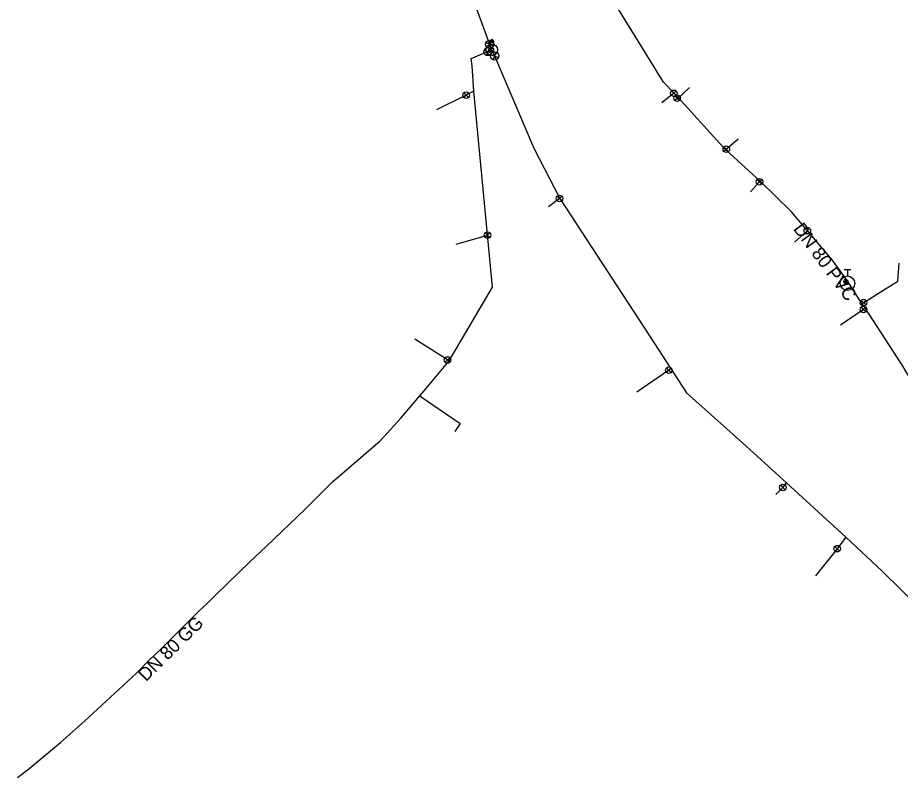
# Model space of a CAD drawing. Extents: x -484784 to -484458, y -1128042 to -1127614.
# Drawn here: x -484753.5 to -484646.3, y -1127810.6 to -1127718.4 of the extents above; entities that cross this region are included whole.
import ezdxf

# ---------------------------------------------------------------- set-up
doc = ezdxf.new("R2010")
doc.units = 0
for name, color, linetype in [('_hydrantova_odbocka_', 7, 'Continuous'), ('_pripojka_prevzato_z_dokumentace_', 7, 'Continuous'), ('_pripojka_priblizne_', 7, 'Continuous'), ('_voda_smvak_prevzato_z_dokumentace_', 7, 'Continuous'), ('Default', 7, 'Continuous'), ('MoLevel 27', 7, 'Continuous'), ('MoLevel 28', 7, 'Continuous'), ('MoLevel 30', 7, 'Continuous'), ('MoLevel 42', 7, 'Continuous'), ('MoLevel 46', 7, 'Continuous'), ('MoLevel 53', 7, 'Continuous')]:
    doc.layers.add(name, color=color, linetype=linetype)

# ---------------------------------------------------------------- blocks, each defined once
blk = doc.blocks.new('_uzaver_')
at = {"layer": 'Default'}
for p, q in [((-0.000035, -0.000035), (0.000035, 0.000035)), ((0.000035, -0.000035), (-0.000035, 0.000035))]:
    blk.add_line(p, q, dxfattribs=at)
for radius in [0.00005, 0.0000025]:
    blk.add_circle((0, 0), radius, dxfattribs=at)
blk = doc.blocks.new('_uzaver_pripojka_')
at = {"layer": 'Default'}
for p, q in [((-0.000035, -0.000035), (0.000035, 0.000035)), ((0.000035, -0.000035), (-0.000035, 0.000035))]:
    blk.add_line(p, q, dxfattribs=at)
for radius in [0.00005, 0.0000025]:
    blk.add_circle((0, 0), radius, dxfattribs=at)
blk = doc.blocks.new('_hydrant_voda_')
at = {"layer": 'Default'}
for p, q in [((-0.0000225, 0.000095), (0.0000225, 0.000095)), ((0, 0.000095), (0, 0.00005))]:
    blk.add_line(p, q, dxfattribs=at)
blk.add_circle((0, 0), 0.00005, dxfattribs=at)
blk = doc.blocks.new('_sachta_voda_')
at = {"layer": 'Default'}
blk.add_line((-0.00001, 0.000045), (0.00001, 0.000045), dxfattribs=at)
blk.add_lwpolyline([(-0.00001, 0.000035), (-0.00001, 0.00005), (0, 0.000065), (0.00001, 0.00005), (0.00001, 0.000035)], dxfattribs=at)
blk.add_circle((0, 0), 0.000035, dxfattribs=at)
blk = doc.blocks.new('_poklop_voda_')
at = {"layer": 'Default'}
blk.add_lwpolyline([(-0.00002, 0.00002), (0.00002, 0.00002), (0.00002, -0.00002), (-0.00002, -0.00002), (-0.00002, 0.00002)], dxfattribs=at)

msp = doc.modelspace()

# ---------------------------------------------------------------- linework, layer by layer
at = {"layer": '_hydrantova_odbocka_'}
msp.add_lwpolyline([(-484652.74, -1127750.29), (-484652.91, -1127750.43), (-484652.7, -1127750.64)], dxfattribs=at)
at = {"layer": '_pripojka_prevzato_z_dokumentace_'}
msp.add_line((-484659.14, -1127745.67), (-484657.58, -1127744.26), dxfattribs=at)
for points in [[(-484673.29, -1127728.06), (-484673.4, -1127728.16), (-484673.47, -1127728.22), (-484673.38, -1127728.31), (-484671.88, -1127726.88)], [(-484698.08, -1127727.31), (-484699.02, -1127727.8), (-484702.63, -1127729.59)], [(-484673.76, -1127727.55), (-484673.8, -1127727.58), (-484675.26, -1127728.75)], [(-484667.45, -1127734.47), (-484667.42, -1127734.36), (-484665.99, -1127733.1)], [(-484663.3, -1127738.25), (-484663.4, -1127738.32), (-484664.48, -1127739.54)], [(-484687.62, -1127740.36), (-484687.68, -1127740.36), (-484689, -1127741.37)], [(-484649.04, -1127751.92), (-484646.57, -1127750.38), (-484646.44, -1127748.22)], [(-484650.95, -1127753.11), (-484650.76, -1127753), (-484649.04, -1127751.92)], [(-484650.61, -1127753.6), (-484650.75, -1127753.82), (-484653.53, -1127755.74)], [(-484674.21, -1127760.95), (-484674.41, -1127761.21), (-484678.28, -1127763.87)], [(-484661.39, -1127776.29), (-484660.56, -1127775.44), (-484660.1, -1127774.89)], [(-484652.89, -1127781.48), (-484653.94, -1127782.87), (-484656.59, -1127786.17)]]:
    msp.add_lwpolyline(points, dxfattribs=at)
at = {"layer": '_pripojka_priblizne_'}
msp.add_line((-484700.25, -1127745.89), (-484696.41, -1127744.81), dxfattribs=at)
for points in [[(-484701.07, -1127760.05), (-484701.29, -1127759.96), (-484705.25, -1127757.44)], [(-484704.64, -1127764.33), (-484704.47, -1127764.42), (-484699.74, -1127767.67), (-484700.4, -1127768.63)]]:
    msp.add_lwpolyline(points, dxfattribs=at)
at = {"layer": '_voda_smvak_prevzato_z_dokumentace_'}
for p, q in [((-484695.9, -1127722.31), (-484696.15, -1127721.64)), ((-484696.38, -1127722.52), (-484695.9, -1127722.31)), ((-484695.9, -1127722.31), (-484695.56, -1127723.04))]:
    msp.add_line(p, q, dxfattribs=at)
for points in [[(-484696.15, -1127721.64), (-484696.87, -1127719.68), (-484701.22, -1127707.9), (-484706.63, -1127694.26), (-484709.08, -1127689.93), (-484711.43, -1127684.86), (-484712.44, -1127683.11)], [(-484643.08, -1127765.34), (-484645.56, -1127761.38), (-484646.12, -1127760.52), (-484650.61, -1127753.6), (-484650.95, -1127753.11), (-484652.74, -1127750.29), (-484654.58, -1127747.8), (-484659.5, -1127741.98), (-484663.3, -1127738.25), (-484667.45, -1127734.47), (-484668.22, -1127733.67), (-484673.26, -1127728.1), (-484673.76, -1127727.55), (-484675.04, -1127726.21), (-484681.24, -1127716.17), (-484682.76, -1127712.65), (-484683.58, -1127711.28), (-484684.33, -1127709.73), (-484687.86, -1127701.92), (-484687.92, -1127701.76), (-484691.71, -1127695.75), (-484698.39, -1127690.88), (-484712.1, -1127682.86)], [(-484753.49, -1127810.63), (-484753.17, -1127810.41), (-484752.12, -1127809.61), (-484748.28, -1127806.41), (-484745.39, -1127803.79), (-484739.05, -1127797.97), (-484737.46, -1127796.37), (-484736.15, -1127795.09), (-484731.43, -1127790.43), (-484730.44, -1127789.47), (-484729.4, -1127788.46), (-484725.31, -1127784.47), (-484723.32, -1127782.6), (-484718.57, -1127778.07), (-484715.25, -1127774.76), (-484709.45, -1127769.78), (-484706.97, -1127767.02), (-484704.64, -1127764.33), (-484704.1, -1127763.7), (-484701.07, -1127760.05), (-484695.81, -1127751.1), (-484698.08, -1127727.31), (-484698.29, -1127724.26), (-484698.39, -1127723.37), (-484696.38, -1127722.52)], [(-484695.56, -1127723.04), (-484690.81, -1127734.23), (-484687.62, -1127740.36), (-484676.16, -1127757.95), (-484674.21, -1127760.95), (-484672.26, -1127763.95), (-484665.44, -1127770.01), (-484660.1, -1127774.89), (-484652.89, -1127781.48), (-484648.49, -1127785.58), (-484632.11, -1127801.7)]]:
    msp.add_lwpolyline(points, dxfattribs=at)

# ---------------------------------------------------------------- block references
at = {"layer": 'MoLevel 27'}
for p, xscale, yscale, rotation in [((-484696.38, -1127722.52), 9999.999999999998, 9999.999999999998, -156.97097945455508), ((-484696.15, -1127721.64), 10000, 10000, 110.303081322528), ((-484695.56, -1127723.04), 10000.000000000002, 9999.999999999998, -67.18593646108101), ((-484652.91, -1127750.43), 5000, 5000, -45.00000001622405)]:
    msp.add_blockref('_uzaver_', p, dxfattribs=dict(at, xscale=xscale, yscale=yscale, rotation=rotation))
at = {"layer": 'MoLevel 28', "xscale": 17636.68430335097, "yscale": 17636.68430335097}
msp.add_blockref('_hydrant_voda_', (-484652.7, -1127750.64), dxfattribs=at)
at = {"layer": 'MoLevel 30', "xscale": 20000, "yscale": 20000}
msp.add_blockref('_sachta_voda_', (-484695.9, -1127722.31), dxfattribs=at)
at = {"layer": 'MoLevel 42', "xscale": 10000, "yscale": 10000}
msp.add_blockref('_poklop_voda_', (-484695.9, -1127722.31), dxfattribs=at)
at = {"layer": 'MoLevel 53', "xscale": 7999.999999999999, "yscale": 7999.999999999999}
for p in [(-484673.8, -1127727.58), (-484699.02, -1127727.8), (-484673.4, -1127728.16), (-484667.42, -1127734.36), (-484663.4, -1127738.32), (-484687.68, -1127740.36), (-484696.41, -1127744.81), (-484657.58, -1127744.26), (-484650.76, -1127753), (-484650.75, -1127753.82), (-484701.29, -1127759.96), (-484674.41, -1127761.21), (-484660.56, -1127775.44), (-484653.94, -1127782.87)]:
    msp.add_blockref('_uzaver_pripojka_', p, dxfattribs=at)

# ---------------------------------------------------------------- texts
at = {"layer": 'MoLevel 46'}
for s, rotation, p in [('DN 80 PVC', 306.5101, (-484659.36, -1127744.05)), ('DN 80 GG', 44.6149, (-484737.91, -1127799.08))]:
    msp.add_text(s, height=1.605, rotation=rotation, dxfattribs=at).set_placement(p)

doc.saveas('drawing.dxf')
